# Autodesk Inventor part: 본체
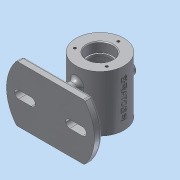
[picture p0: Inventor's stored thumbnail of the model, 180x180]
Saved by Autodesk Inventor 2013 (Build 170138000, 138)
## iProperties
Created: 2017-12
Part Number: 본체
Material: 알루미늄 6061
Document SubType Name: Modeling
Designer: dgall
Density: 2.71 g/cm^3
Mass: 467.691 g
Surface Area: 486.473 cm^2
Volume: 172.58 cm^3
Author: dgall
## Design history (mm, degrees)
sketch "스케치1"
  geometry: C1 r 30 at (0, 0); 1 further point
  constraints: 1 centre point, 1 coincident
  dimensions: "d0" = 60 diameter of C1
extrude "돌출1" new body sketch "스케치1" stored distance "d2" = 70; taper "d3" = 0 deg
node "작업 평면1"
node "작업 평면2"
node "작업 평면3"
node "작업 평면4"
sketch "스케치5"
  geometry: C1 r 8 at (0, 0); 1 further point
  constraints: 1 centre point, 1 coincident
  dimensions: "d23" = 16 diameter of C1
extrude "돌출5" join sketch "스케치5" stored distance "d25" = 10; taper "d26" = 0 deg
node "작업 평면5"
sketch "스케치6"
  geometry: L1 (30, 35)-(-30, 35) reference; L2 (-30, -35)-(30, -35) reference; L3 (0, 35)-(0, -35); L4 (16, 35)-(16, 23.3); L5 (15.7, 23)-(14, 23); L6 (14, 23)-(14, 20); L7 (14, 20)-(22, 20); L8 (25, 17)-(25, -17); L9 (22, -20)-(14, -20); L10 (14, -20)-(14, -23); L11 (14, -23)-(15.7, -23); L12 (16, -23.3)-(16, -35); L13 (16, 35)-(0, 35); L14 (16, -35)-(0, -35); A1 r 3 centre (22, -17) between (22, -20) and (25, -17); A2 r 3 centre (22, 17) between (25, 17) and (22, 20); A3 r 0.3 centre (15.7, 23.3) between (15.7, 23) and (16, 23.3); A4 r 0.3 centre (15.7, -23.3) between (16, -23.3) and (15.7, -23); 5 further points
  constraints: 24 end point, 10 point on line, 8 point on circle, 8 tangent, 7 parallel, 4 centre point, 3 collinear, 2 equal radius, 2 midpoint, 2 perpendicular, 2 vertical alignment
  dimensions: "d27" = 32 diameter of L4 L3; "d29" = 28 diameter of L6 L3; "d30" = 50 diameter of L8 L3; "d31" = 40 distance of point (25, 20) point (25, -20); "d32" = 12 distance of point (16, -23) L12.end; "d33" = 3 distance of L9.end L10.end; "d34" = 3 radius of A1; "d35" = 0.3 radius of A3
revolve "회전1" sketch "스케치6" stored, may be unused: angle "d36" = 90 deg
chamfer "모따기1" distance "d37" = 1; stored, may be unused: second distance "d38" = 2, angle "d39" = 45 deg
chamfer "모따기2" distance "d40" = 1; stored, may be unused: second distance "d41" = 2, angle "d42" = 45 deg
hole "구멍1" diameter "d45" = 8; stored, may be unused: countersink angle "d49" = 90 deg, drill point angle "d51" = 0 deg; dims "d43" = 10, "d44" = 10, "d46" = 6, "d47" = 4, "d48" = 2, "d50" = 25
chamfer "모따기3" distance "d52" = 1; stored, may be unused: second distance "d53" = 2, angle "d54" = 45 deg
fillet "모깎기1" dims "d55" = 3
sketch "스케치7"
  geometry: L1 (-42.426, 35)-(42.426, 35); L2 (-42.426, -35)-(42.426, -35); A1 r 55 centre (0, 0) between (-42.426, 35) and (-42.426, -35); A2 r 55 centre (0, 0) between (42.426, -35) and (42.426, 35); 3 further points
  constraints: 4 end point, 4 point on circle, 2 centre point, 2 coincident, 2 concentric, 2 midpoint, 2 parallel, 2 vertical alignment, 1 horizontal
  dimensions: "d58" = 70 distance between parallel lines of L2 L1; "d59" = 110 diameter of A1
extrude "돌출6" join sketch "스케치7" distance "d60" = 10; taper "d61" = 0 deg
sketch "스케치8"
  geometry: L1 (-40, 5)-(-24, 5); L2 (-40, -5)-(-24, -5); L3 (-5, 15)-(-5, -15); L4 (5, 15)-(5, -15); A1 r 55 centre (0, 0) between (42.426, -35) and (42.426, 35) reference; A2 r 5 centre (-40, 0) between (-40, 5) and (-40, -5); A3 r 5 centre (-24, 0) between (-24, -5) and (-24, 5); A4 r 5 centre (0, 15) between (5, 15) and (-5, 15); A5 r 5 centre (0, -15) between (-4.969, -14.448) and (5, -15)
  constraints: 9 point on circle, 8 end point, 4 centre point, 4 tangent, 3 parallel, 2 equal radius, 2 horizontal alignment, 2 vertical alignment, 1 vertical
  dimensions: "d62" = 5 radius of A2; "d64" = 24 distance of A1.centre A3.centre; "d65" = 40 distance of A1.centre A2.centre; "d66" = 5 radius of A4; "d67" = 30 distance of A5.centre A4.centre; "d68" = 15 distance of A1.centre A4.centre
extrude "돌출7" join sketch "스케치8" stored distance "d69" = 10; taper "d70" = 0 deg
extrude "돌출8" cut sketch "스케치8" stored distance "d71" = 10; taper "d72" = 0 deg
sketch "스케치9" dims "d73" = 46
  geometry: L1 (0, 0)-(0, 23); C1 r 17 at (0, 0) reference
  constraints: 2 end point, 1 coincident, 1 vertical, 1 vertical alignment, 2 other
hole "구멍2" sketch "스케치9" at (0, 23) diameter "d75" = 3.242; stored, may be unused: countersink angle "d79" = 90 deg, drill point angle "d81" = 118 deg; dims "d76" = 8, "d77" = 4, "d78" = 2, "d80" = 10
fillet "모깎기2" dims "d85" = 5
fillet "모깎기3" dims "d86" = 3
fillet "모깎기4" dims "d87" = 3
node "작업 평면7"
  node "작업 평면6"
sketch "스케치10"
  geometry: L1 (30, 35)-(-30, 35) reference; 2 further points
  constraints: 1 other
  dimensions: "d89" = 35 distance from line of L1 point (0, 0); "d90" = 30 horizontal distance of L1.start point (0, 0)
feature "엠보싱1" sketch "스케치10" dims "d2" = 70, "d27" = 32, "d29" = 28, "d30" = 50, "d31" = 40, "d32" = 12, "d33" = 3, "d34" = 3, "d35" = 0.3, "d91" = 0.5, "d92" = 0
node "솔리드1"
mirror "대칭2"
pattern_circular "원형 패턴1" dims angle "d83" = 360 deg
mirror "대칭3"
other parameters: "d4" = -62, "d22" = 37
